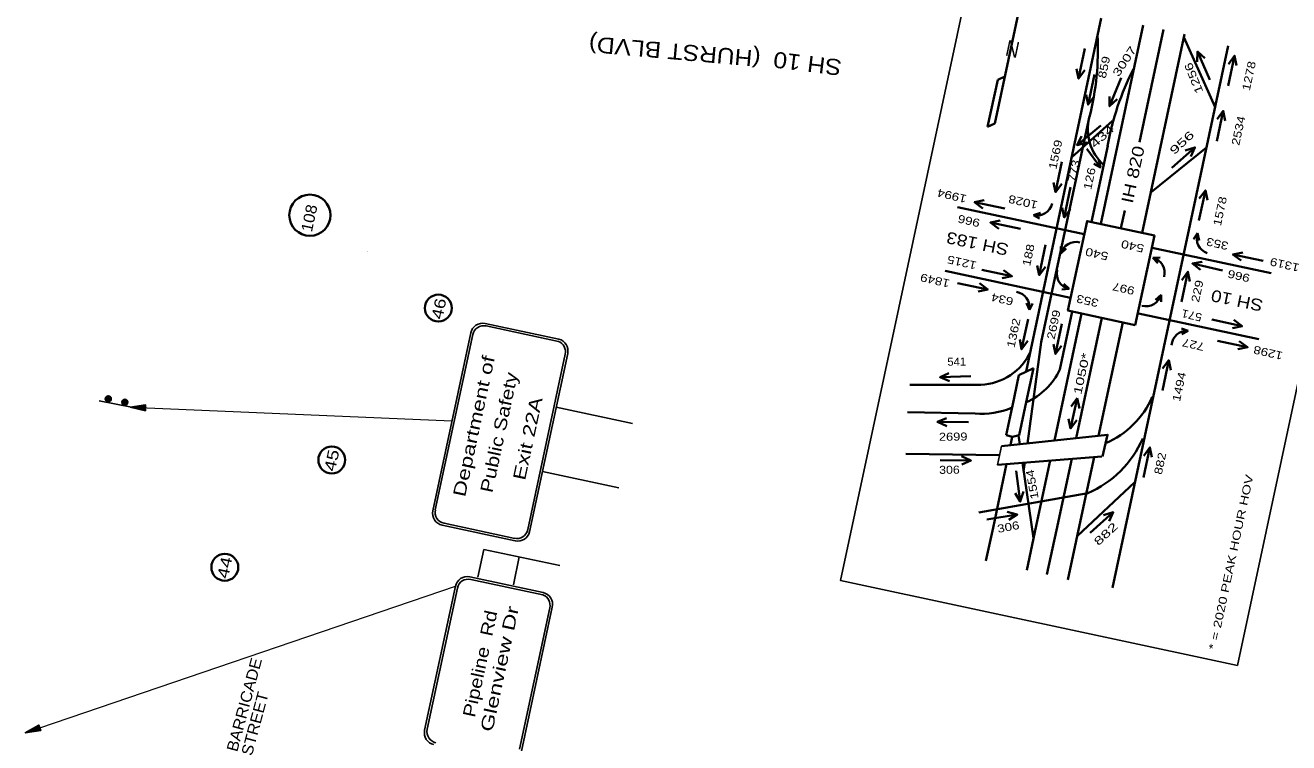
# Model space of a CAD drawing. Extents: x 2363411 to 2369702, y 6977197 to 6988655.
# Drawn here: x 2364967 to 2366546, y 6979621 to 6980518 of the extents above; entities that cross this region are included whole.
import ezdxf
from ezdxf.enums import TextEntityAlignment as Align

# ---------------------------------------------------------------- set-up
doc = ezdxf.new("R2010")
doc.units = 0
doc.header["$LTSCALE"] = 5.6
for name, color, linetype, lineweight in [('1', 7, 'Continuous', 25), ('13', 7, 'Continuous', 13), ('17', 7, 'Continuous', 35), ('55', 7, 'Continuous', 35), ('61', 7, 'Continuous', 25)]:
    doc.layers.add(name, color=color, linetype=linetype, lineweight=lineweight)

msp = doc.modelspace()

# ---------------------------------------------------------------- hatches: boundary and pattern name
at = {"layer": '1'}
for points in [[(2365068.3, 6980048.309, 1), (2365073.784, 6980053.371, 1)], [(2365088.899, 6980043.908, 1), (2365094.384, 6980048.97, 1)], [(2365098.39, 6980040.183), (2365117.45, 6980035.91), (2365117.708, 6980043.107)], [(2364967.256, 6979633.295), (2364986.566, 6979636.231), (2364984.194, 6979643.032)]]:
    msp.add_hatch(color=256, dxfattribs=at).paths.add_polyline_path(points)

# ---------------------------------------------------------------- linework, layer by layer
for p, q in [((2365542.007, 6980145.004), (2365633.945, 6980125.358)), ((2365524.152, 6980133.436), (2365476.581, 6979910.78)), ((2365526.518, 6980131.007), (2365479.722, 6979912.034)), ((2365633.479, 6980122.566), (2365543.261, 6980141.847)), ((2365595.245, 6979887.351), (2365642.071, 6980106.509)), ((2365597.549, 6979884.625), (2365645.117, 6980107.276)), ((2365100.111, 6980040.222), (2365059.743, 6980048.483)), ((2365630.82, 6980040.357), (2365726.072, 6980020.005)), ((2365613.613, 6979959.816), (2365708.865, 6979939.464)), ((2365488.147, 6979892.915), (2365579.469, 6979873.4)), ((2365490.583, 6979895.285), (2365578.884, 6979876.415)), ((2365532.75, 6979827.921), (2365540.179, 6979862.695)), ((2365540.179, 6979862.695), (2365635.431, 6979842.342)), ((2365577.253, 6979818.416), (2365584.683, 6979853.186)), ((2365522.729, 6979828.257), (2365614.667, 6979808.611)), ((2365504.879, 6979816.692), (2365466.378, 6979636.506)), ((2365507.24, 6979814.263), (2365469.519, 6979637.76)), ((2365614.201, 6979805.819), (2365523.983, 6979825.1)), ((2365585.042, 6979613.077), (2365622.798, 6979789.762)), ((2365587.346, 6979610.351), (2365625.84, 6979790.529))]:
    msp.add_line(p, q, dxfattribs=at)
at = {"layer": '1', "lineweight": 13}
for p, q in [((2365100.111, 6980040.222), (2365500.246, 6980023.372)), ((2364967.256, 6979633.295), (2365504.879, 6979816.692))]:
    msp.add_line(p, q, dxfattribs=at)
at = {"layer": '1'}
for points in [[(2365098.39, 6980040.183), (2365117.45, 6980035.91), (2365117.708, 6980043.107)], [(2364967.256, 6979633.295), (2364986.566, 6979636.231), (2364984.194, 6979643.032)]]:
    msp.add_lwpolyline(points, close=True, dxfattribs=at)
for centre in [(2365071.042, 6980050.84), (2365091.641, 6980046.439)]:
    msp.add_circle(centre, 3.732, dxfattribs=at)
for centre, radius, start, end in [((2365427.856, 6980296.69), 69.535, 241.59391, 241.7489), ((2365538.869, 6980130.291), 15.049, 77.93925, 169.35675), ((2365540.315, 6980128.058), 14.108, 77.93925, 167.93925), ((2365628.275, 6980109.456), 14.108, 347.93925, 68.3439), ((2365630.468, 6980110.719), 15.049, 346.76968, 76.63979), ((2365491.297, 6979907.637), 15.049, 167.93925, 257.93925), ((2365493.53, 6979909.084), 14.108, 167.93925, 257.93925), ((2365581.45, 6979890.298), 14.108, 257.93925, 347.93925), ((2365582.896, 6979888.066), 15.049, 257.93925, 346.76968), ((2365519.59, 6979813.545), 15.049, 77.93925, 169.35675), ((2365521.037, 6979811.313), 14.108, 77.93925, 167.93925), ((2365608.996, 6979792.711), 14.108, 347.93925, 68.3439), ((2365611.189, 6979793.974), 15.049, 346.76968, 76.63979), ((2365481.093, 6979633.364), 15.049, 167.93925, 257.93925), ((2365483.326, 6979634.811), 14.108, 167.93925, 257.93925)]:
    msp.add_arc(centre, radius, start, end, dxfattribs=at)
at = {"layer": '17'}
for centre, radius in [((2365322.928, 6980280.303), 25.72), ((2365483.544, 6980164.167), 16.828), ((2365350.342, 6979974.411), 16.828), ((2365216.627, 6979840.361), 16.828)]:
    msp.add_circle(centre, radius, dxfattribs=at)
at = {"layer": '55'}
for p, q in [((2366178.944, 6980394.843), (2366217.725, 6980576.345)), ((2366311.984, 6980526.529), (2366218.153, 6980084.816)), ((2366311.224, 6980269.361), (2366364.263, 6980517.591)), ((2366359.585, 6980371.489), (2366389.644, 6980512.168)), ((2366362.865, 6980258.327), (2366415.903, 6980506.557)), ((2366454.294, 6980415.252), (2366415.204, 6980502.713)), ((2366432.136, 6980484.798), (2366431.901, 6980471.849)), ((2366478.597, 6980479.519), (2366470.829, 6980469.159)), ((2366283.53, 6980450.995), (2366291.297, 6980461.357)), ((2366169.962, 6980390.666), (2366182.499, 6980449.343)), ((2366182.499, 6980449.343), (2366191.482, 6980453.521)), ((2366295.495, 6980418.44), (2366303.262, 6980428.802)), ((2366322.4, 6980416.417), (2366331.869, 6980425.253)), ((2366297.395, 6980403.953), (2366237.036, 6980121.466)), ((2366325.861, 6980398.326), (2366275.088, 6980352.839)), ((2366464.464, 6980410.515), (2366456.695, 6980400.153)), ((2366169.962, 6980390.666), (2366178.944, 6980394.843)), ((2366281.705, 6980367.817), (2366294.214, 6980371.167)), ((2366320.023, 6980367.055), (2366299.676, 6980271.828)), ((2366310.827, 6980339.938), (2366308.895, 6980349.457)), ((2366374.362, 6980309.201), (2366443.507, 6980364.911)), ((2366429.02, 6980364.978), (2366416.619, 6980361.242)), ((2366254.811, 6980309.083), (2366262.58, 6980319.445)), ((2366442.044, 6980311.309), (2366434.275, 6980300.946)), ((2366132.119, 6980290.362), (2366290.654, 6980256.488)), ((2366153.621, 6980296.48), (2366164.023, 6980288.766)), ((2366265.627, 6980277.486), (2366273.394, 6980287.848)), ((2366336.605, 6980263.938), (2366341.386, 6980286.312)), ((2366173.396, 6980271.025), (2366183.792, 6980263.302)), ((2366227.167, 6980280.305), (2366235.916, 6980283.304)), ((2366227.167, 6980280.305), (2366234.877, 6980275.96)), ((2366432.322, 6980257.699), (2366427.25, 6980250.446)), ((2366432.322, 6980257.699), (2366434.459, 6980248.699)), ((2366261.479, 6980232.206), (2366261.252, 6980241.056)), ((2366375.565, 6980239.424), (2366524.289, 6980207.646)), ((2366261.479, 6980232.206), (2366268.228, 6980238.534)), ((2366376.568, 6980227.157), (2366385.418, 6980227.329)), ((2366376.568, 6980227.157), (2366382.853, 6980220.369)), ((2366476.547, 6980231.36), (2366486.909, 6980223.592)), ((2366116.687, 6980210.556), (2366273.673, 6980177.013)), ((2366200.209, 6980204.013), (2366189.846, 6980211.781)), ((2366234.37, 6980205.352), (2366242.139, 6980215.714)), ((2366420.304, 6980209.564), (2366412.536, 6980199.202)), ((2366425.791, 6980219.798), (2366436.015, 6980211.849)), ((2366170.09, 6980187.572), (2366159.708, 6980195.313)), ((2366271.697, 6980188.172), (2366265.125, 6980194.681)), ((2366271.697, 6980188.172), (2366262.864, 6980187.615)), ((2366386.772, 6980180.917), (2366379.938, 6980174.683)), ((2366386.772, 6980180.917), (2366386.878, 6980172.066)), ((2366222.063, 6980161.842), (2366218.489, 6980170.374)), ((2366222.063, 6980161.842), (2366225.886, 6980169.825)), ((2366275.748, 6980159.84), (2366260.301, 6980087.549)), ((2366253.387, 6979998.675), (2366287.296, 6980157.373)), ((2366280.561, 6980001.643), (2366312.677, 6980151.95)), ((2366308.676, 6980004.716), (2366338.936, 6980146.339)), ((2366358.549, 6980157.259), (2366508.823, 6980125.15)), ((2366487.916, 6980141.523), (2366477.593, 6980149.344)), ((2366420.577, 6980135.879), (2366412.239, 6980138.85)), ((2366420.577, 6980135.879), (2366412.463, 6980131.435)), ((2366212.47, 6980112.787), (2366220.237, 6980123.148)), ((2366237.036, 6980121.466), (2366219.707, 6979994.994)), ((2366254.633, 6980106.818), (2366262.402, 6980117.178)), ((2366494.81, 6980115.17), (2366484.449, 6980122.938)), ((2366396.37, 6980098.906), (2366388.602, 6980088.543)), ((2366209.061, 6980080.513), (2366227.245, 6980089.119)), ((2366227.245, 6980089.119), (2366218.189, 6980046.49)), ((2366161.388, 6980068.346), (2366072.709, 6980068.34)), ((2366110.448, 6980077.703), (2366122.373, 6980072.654)), ((2366209.061, 6980080.513), (2366200.404, 6980039.765)), ((2366203.016, 6980052.061), (2366193.137, 6980005.547)), ((2366281.718, 6980051.417), (2366274.498, 6980041.355)), ((2366281.718, 6980051.417), (2366284.574, 6980038.785)), ((2366154.365, 6980032.533), (2366069.696, 6980034.115)), ((2366218.188, 6980046.49), (2366209.421, 6980005.211)), ((2366107.283, 6980021.917), (2366119.018, 6980016.437)), ((2366273.663, 6980013.719), (2366281.432, 6980024.081)), ((2366200.812, 6980003.18), (2366198.583, 6979992.686)), ((2366208.373, 6980004.96), (2366209.998, 6979993.934)), ((2366372.799, 6979990.094), (2366365.03, 6979979.733)), ((2366184.236, 6979980.339), (2366067.575, 6979982.155)), ((2366149.086, 6979973.693), (2366137.41, 6979979.298)), ((2366182.079, 6979968.509), (2366312.82, 6979978.516)), ((2366213.393, 6979970.906), (2366227.298, 6979876.576)), ((2366216.439, 6979971.139), (2366214.955, 6979960.311)), ((2366256.032, 6979886.846), (2366275.001, 6979975.621)), ((2366281.771, 6979879.135), (2366354.084, 6979946.825)), ((2366295.055, 6979932.917), (2366159.047, 6979908.778)), ((2366210.803, 6979922.42), (2366214.586, 6979934.806)), ((2366206.905, 6979906.086), (2366194.433, 6979909.579)), ((2366326.985, 6979909.133), (2366314.6, 6979905.347)), ((2366244.111, 6979831.053), (2366256.032, 6979886.846))]:
    msp.add_line(p, q, dxfattribs=at)
for points in [[(2366325.791, 6979814.404), (2366350.511, 6979930.101), (2366470.577, 6980492.025)], [(2366291.584, 6980488.692), (2366283.53, 6980450.995), (2366281.051, 6980463.129)], [(2366447.667, 6980449.516), (2366432.136, 6980484.798), (2366441.247, 6980476.408)], [(2366470.542, 6980441.823), (2366478.597, 6980479.519), (2366481.075, 6980467.387)], [(2366303.549, 6980456.137), (2366295.495, 6980418.44), (2366293.016, 6980430.574)], [(2366336.955, 6980452.112), (2366322.4, 6980416.417), (2366322.094, 6980428.798)], [(2366456.409, 6980372.817), (2366464.464, 6980410.515), (2366466.942, 6980398.381)], [(2366311.325, 6980392.486), (2366281.705, 6980367.817), (2366287.251, 6980378.89)], [(2366293.724, 6980363.248), (2366310.827, 6980339.938), (2366302.793, 6980344.6)], [(2366400.176, 6980339.403), (2366429.02, 6980364.978), (2366423.818, 6980353.737)], [(2366262.866, 6980346.781), (2366254.811, 6980309.083), (2366252.334, 6980321.217)], [(2366273.681, 6980315.183), (2366265.627, 6980277.486), (2366263.148, 6980289.62)], [(2366433.989, 6980273.612), (2366442.044, 6980311.309), (2366444.522, 6980299.174)], [(2366191.359, 6980288.622), (2366153.621, 6980296.48), (2366165.741, 6980299.021)], [(2366211.128, 6980263.134), (2366173.396, 6980271.025), (2366185.52, 6980273.556)], [(2366242.425, 6980243.049), (2366234.37, 6980205.352), (2366231.893, 6980217.486)], [(2366514.244, 6980223.306), (2366476.547, 6980231.36), (2366488.681, 6980233.839)], [(2366162.512, 6980212.068), (2366200.209, 6980204.013), (2366188.074, 6980201.534)], [(2366412.25, 6980171.866), (2366420.304, 6980209.564), (2366422.783, 6980197.43)], [(2366463.34, 6980211.08), (2366425.791, 6980219.798), (2366437.967, 6980222.063)], [(2366132.373, 6980195.527), (2366170.09, 6980187.572), (2366157.963, 6980185.061)], [(2366220.524, 6980150.484), (2366212.47, 6980112.787), (2366209.992, 6980124.92)], [(2366262.688, 6980144.515), (2366254.633, 6980106.818), (2366252.156, 6980118.95)], [(2366450.259, 6980149.769), (2366487.916, 6980141.523), (2366475.769, 6980139.106)], [(2366457.113, 6980123.224), (2366494.81, 6980115.17), (2366482.676, 6980112.691)], [(2366388.315, 6980061.208), (2366396.37, 6980098.906), (2366398.849, 6980086.771)], [(2366148.976, 6980078.948), (2366110.448, 6980077.703), (2366121.63, 6980083.026)], [(2366281.718, 6980051.417), (2366273.663, 6980013.719), (2366271.186, 6980025.853)], [(2366145.832, 6980021.756), (2366107.283, 6980021.917), (2366118.654, 6980026.828)], [(2366313.584, 6979978.574), (2366319.75, 6980005.925), (2366187.175, 6979991.44)], [(2366193.137, 6980005.547), (2366200.874, 6980003.161), (2366209.421, 6980005.211)], [(2366364.744, 6979952.397), (2366372.799, 6979990.094), (2366375.277, 6979977.96)], [(2366110.541, 6979974.264), (2366149.086, 6979973.693), (2366137.665, 6979968.903)], [(2366218.73, 6979836.476), (2366230.651, 6979892.269), (2366248.02, 6979973.557)], [(2366270.207, 6979824.674), (2366291.05, 6979922.227), (2366302.916, 6979977.758)], [(2366193.635, 6979969.393), (2366176.686, 6979889.607), (2366167.877, 6979848.141)], [(2366205.563, 6979960.611), (2366210.803, 6979922.42), (2366204.348, 6979932.99)], [(2366298.247, 6979883.441), (2366326.985, 6979909.133), (2366321.829, 6979897.872)], [(2366168.846, 6979899.956), (2366206.905, 6979906.086), (2366196.489, 6979899.386)]]:
    msp.add_lwpolyline(points, dxfattribs=at)
msp.add_lwpolyline([(2366354.428, 6980143.029), (2366378.357, 6980255.017), (2366294.183, 6980273.002), (2366270.254, 6980161.014)], close=True, dxfattribs=at)
for centre, radius, start, end in [((2365967.693, 6980487.052), 340.052, 345.75594, 2.95402), ((2366654.895, 6980308.155), 340.052, 152.92411, 170.12219), ((2366354.759, 6980387.57), 59.594, 165.58608, 228.066), ((2366231.64, 6980299.509), 19.717, 256.88685, 345.85814), ((2366451.002, 6980251.383), 19.717, 161.31818, 250.28947), ((2366280.54, 6980227.163), 19.717, 76.20836, 165.17964), ((2366371.408, 6980208.127), 19.717, 345.85767, 74.82896), ((2366276.03, 6980207.407), 19.717, 168.33421, 257.3055), ((2366202.604, 6980165.029), 19.717, 350.69851, 79.6698), ((2366367.783, 6980186.221), 19.717, 255.42281, 344.39409), ((2366419.433, 6980116.194), 19.717, 86.6755, 175.64679), ((2366158.781, 6980139.323), 71.024, 272.10333, 335.70475), ((2366185.706, 6980121.933), 82.138, 293.29501, 335.25369), ((2366272.524, 6980098.828), 112.891, 293.38713, 336.10299), ((2366162.938, 6980128.116), 95.967, 264.87526, 292.97961), ((2366242.306, 6980054.889), 132.891, 293.38713, 336.10299)]:
    msp.add_arc(centre, radius, start, end, dxfattribs=at)
at = {"layer": '61'}
msp.add_line((2366182.079, 6979968.509), (2366187.175, 6979991.44), dxfattribs=at)
msp.add_lwpolyline([(2366482.339, 6979717.696), (2366663.815, 6980567.032), (2366167.737, 6980673.028), (2365986.261, 6979823.692)], close=True, dxfattribs=at)

# ---------------------------------------------------------------- texts
at = {"layer": '1'}
for s, width, p in [('Department of', 1.35, (2365535.589, 6980014.988)), ('Public Safety', 1.25, (2365566.92, 6980007.22)), ('Exit 22A', 1.35, (2365602.803, 6979999.551)), ('Pipeline  Rd', 1.2, (2365543.274, 6979718.139)), ('Glenview Dr', 1.4, (2365567.681, 6979711.85))]:
    msp.add_text(s, height=15.68, rotation=77.939, dxfattribs=dict(at, width=width)).set_placement(p, align=Align.CENTER)
at = {"layer": '1', "width": 1.1}
for s, p in [('BARRICADE ', (2365232.095, 6979608.769)), ('STREET', (2365250.443, 6979603.833))]:
    msp.add_text(s, height=14, rotation=74.944, dxfattribs=at).set_placement(p)
at = {"layer": '13', "width": 1.15}
for s, rotation, p in [('(HURST BLVD)', 174.988, (2365886.924, 6980485.385)), ('SH 10', 172.976, (2365988.47, 6980474.368))]:
    msp.add_text(s, height=20, rotation=rotation, dxfattribs=at).set_placement(p)
at = {"layer": '17'}
for s, width, p in [('108', 1.1, (2365328.999, 6980275.192)), ('46', 1.25, (2365490.977, 6980162.03)), ('45', 1.3, (2365357.075, 6979972.423)), ('44', 1.3, (2365223.36, 6979838.374))]:
    msp.add_text(s, height=14, rotation=77.939, dxfattribs=dict(at, width=width)).set_placement(p, align=Align.CENTER)
at = {"layer": '55'}
for s, height, rotation, width, p in [('N', 20, 347.939, 0.85, (2366199.001, 6980478.27)), ('3007', 10, 56.669, 1.4, (2366345.147, 6980469.793)), ('859', 10, 77.939, 1.25, (2366320.305, 6980464.111)), ('1256', 10, 112.017, 1.35, (2366432.094, 6980453.472)), ('1278', 10, 77.939, 1.25, (2366501.411, 6980453.338)), ('2534', 10, 77.939, 1.25, (2366488.195, 6980384.868)), ('434', 10, 42.878, 1.55, (2366316.509, 6980375.097)), ('956', 10, 42.878, 1.6, (2366416.096, 6980367.375)), ('1569', 10, 77.939, 1.25, (2366259.592, 6980355.056)), ('IH 820', 14.7, 77.939, 1.25, (2366358.74, 6980329.655)), ('773', 10, 77.939, 1.25, (2366282.582, 6980334.482)), ('126', 10, 77.939, 1.25, (2366302.209, 6980324.976)), ('1994', 10, 167, 1.25, (2366126.453, 6980309.297)), ('1028', 10, 167, 1.25, (2366215.329, 6980301.614)), ('1578', 10, 77.939, 1.25, (2366465.283, 6980284.253)), ('966', 10, 167, 1.25, (2366147.645, 6980278.017)), ('SH 183', 14.7, 168.309, 1.2, (2366158.767, 6980251.931)), ('188', 10, 77.939, 1.25, (2366225.857, 6980229.416)), ('540', 10, 167, 1.3, (2366307.561, 6980236.621)), ('540', 10, 167, 1.3, (2366352.234, 6980246.349)), ('353', 10, 167, 1.25, (2366458.17, 6980249.411)), ('1215', 10, 167, 1.25, (2366138.904, 6980226.081)), ('1319', 10, 167, 1.25, (2366542.278, 6980223.276)), ('1849', 10, 167, 1.25, (2366105.279, 6980203.586)), ('966', 10, 167, 1.25, (2366484.933, 6980209.163)), ('997', 10, 167, 1.25, (2366340.915, 6980193.355)), ('229', 10, 77.939, 1.25, (2366436.852, 6980184.29)), ('634', 10, 167, 1.25, (2366189.377, 6980179.962)), ('353', 10, 167, 1.25, (2366295.863, 6980178.088)), ('SH 10', 14.7, 168.309, 1.2, (2366483.104, 6980180.797)), ('2699', 10, 77.939, 1.25, (2366257.34, 6980142.543)), ('571', 10, 167, 1.15, (2366426.173, 6980159.882)), ('1362', 10, 77.939, 1.25, (2366207.306, 6980132.114)), ('727', 10, 167, 1.25, (2366428.02, 6980123.349)), ('1298', 10, 167, 1.25, (2366521.591, 6980113.219)), ('541', 10, 0.691, 1.05, (2366131.368, 6980092.282)), ('1050*', 10, 77.939, 1.5, (2366292.35, 6980081.074)), ('1494', 10, 77.939, 1.25, (2366414.152, 6980064.813)), ('2699', 10, 0.691, 1.2, (2366126.938, 6979998.549)), ('882', 10, 77.939, 1.25, (2366390.393, 6979969.011)), ('306', 10, 0.691, 1.15, (2366122.29, 6979957.133)), ('1554', 10, 99.854, 1.25, (2366230.56, 6979944.621)), ('* = 2020 PEAK HOUR HOV', 10, 77.939, 1.35, (2366478.927, 6979845.636)), ('306', 10, 10.691, 1.25, (2366196.707, 6979885.752)), ('882', 10, 42.878, 1.55, (2366320.995, 6979878.309))]:
    msp.add_text(s, height=height, rotation=rotation, dxfattribs=dict(at, width=width)).set_placement(p, align=Align.CENTER)

doc.saveas('drawing.dxf')
